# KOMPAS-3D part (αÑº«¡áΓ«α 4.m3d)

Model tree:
1. Эскиз:1
2. Операция выдавливания:1
     Толщина стенки 1 = 2; Толщина стенки 2 = 8; Расстояние 1 = 1
3. Эскиз:3
4. Операция выдавливания:2
     Толщина стенки 1 = 2; Толщина стенки 2 = 6; Расстояние 1 = 5.5
5. Эскиз:4
6. Операция выдавливания:3
     Толщина стенки 1 = 2; Толщина стенки 2 = 6; Расстояние 1 = 1
7. Эскиз:5
8. Эскиз:6
9. Операция выдавливания:4
     Толщина стенки 1 = 2; Толщина стенки 2 = 2.5; Расстояние 1 = 50
10. Эскиз:7
11. Вырезать элемент выдавливания:1
     Толщина стенки 2 = 1.5; Расстояние 1 = 40
12. Эскиз:8
13. Операция выдавливания:5
     Толщина стенки 1 = 2; Толщина стенки 2 = 2.5; Расстояние 1 = 50
14. Эскиз:9
15. Вырезать элемент выдавливания:2
     Толщина стенки 2 = 1.5; Расстояние 1 = 40
16. Эскиз:10
17. Операция выдавливания:6
     Толщина стенки 1 = 2; Толщина стенки 2 = 2.5; Расстояние 1 = 10
18. Эскиз:11
19. Операция выдавливания:7
     Толщина стенки 1 = 2; Толщина стенки 2 = 6; Расстояние 1 = 1
20. Эскиз:12
21. Операция выдавливания:8
     Толщина стенки 1 = 2; Толщина стенки 2 = 6; Расстояние 1 = 5.5
22. Эскиз:13
23. Операция выдавливания:9
     Толщина стенки 1 = 2; Толщина стенки 2 = 8; Расстояние 1 = 1
24. Эскиз:14
25. Вырезать элемент выдавливания:3
     Толщина стенки 2 = 1.5; Расстояние 1 = 23
26. Эскиз:15
27. Вырезать элемент выдавливания:4
     Толщина стенки 2 = 1.5; Расстояние 1 = 1
28. Эскиз:16
29. Вырезать элемент выдавливания:5
     Расстояние 1 = 150
30. Эскиз:19
31. Операция выдавливания:12
     Толщина стенки 1 = 7; Расстояние 1 = 10; Расстояние 2 = 0.4
